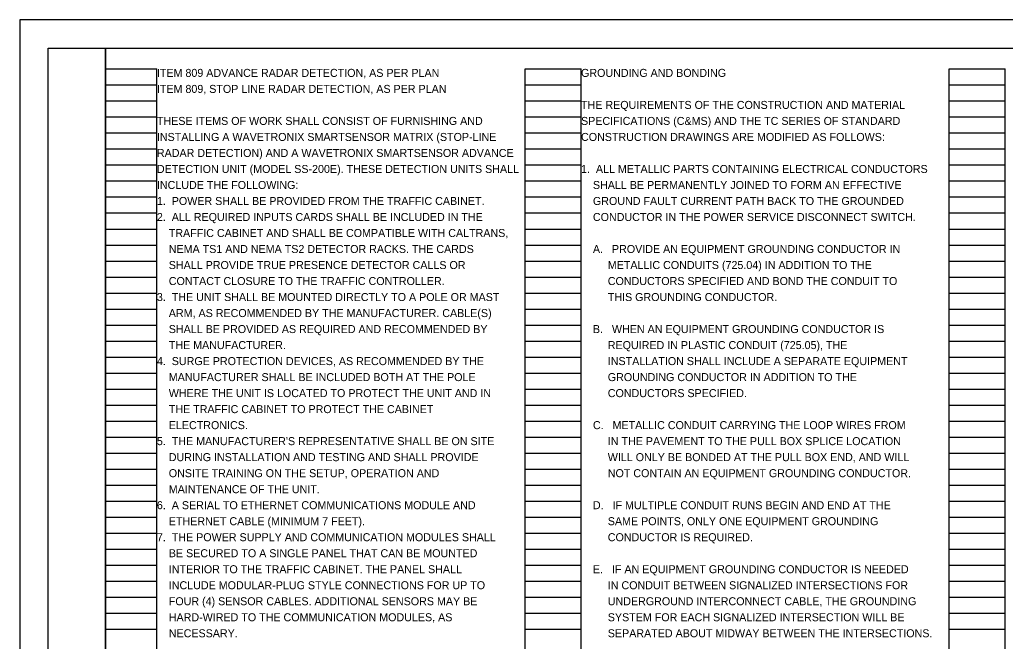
# Model space of a CAD drawing. Extents: x 0 to 34, y 0 to 22.
# Drawn here: x 0 to 17.24, y 11.13 to 22 of the extents above; entities that cross this region are included whole.
import ezdxf

# ---------------------------------------------------------------- set-up
doc = ezdxf.new("R2010")
doc.units = 0
for name, color, linetype in [('SH_Border', 7, 'Continuous'), ('SH_Cut_Line', 7, 'Continuous'), ('SH_Data', 7, 'Continuous'), ('SH_Text', 7, 'Continuous')]:
    doc.layers.add(name, color=color, linetype=linetype)

msp = doc.modelspace()

# ---------------------------------------------------------------- linework, layer by layer
at = {"layer": 'SH_Border'}
for points in [[(0.5, 21.5), (1.5, 21.5), (1.5, 0.5), (0.5, 0.5)], [(1.5, 21.5), (33.5, 21.5), (33.5, 0.5), (1.5, 0.5)]]:
    msp.add_lwpolyline(points, close=True, dxfattribs=at)
at = {"layer": 'SH_Cut_Line'}
msp.add_lwpolyline([(0, 0), (34, 0), (34, 22), (0, 22)], close=True, dxfattribs=at)
at = {"layer": 'SH_Data'}
for p, q in [((1.5, 0.98), (1.5, 21.14)), ((1.5, 21.14), (2.4, 21.14)), ((2.4, 0.98), (2.4, 21.14)), ((8.84, 0.98), (8.84, 21.14)), ((8.84, 21.14), (9.82, 21.14)), ((9.82, 0.98), (9.82, 21.14)), ((16.26, 0.98), (16.26, 21.14)), ((16.26, 21.14), (17.24, 21.14)), ((17.24, 0.98), (17.24, 21.14)), ((1.5, 20.86), (2.4, 20.86)), ((8.84, 20.86), (9.82, 20.86)), ((16.26, 20.86), (17.24, 20.86)), ((1.5, 20.58), (2.4, 20.58)), ((8.84, 20.58), (9.82, 20.58)), ((16.26, 20.58), (17.24, 20.58)), ((1.5, 20.3), (2.4, 20.3)), ((8.84, 20.3), (9.82, 20.3)), ((16.26, 20.3), (17.24, 20.3)), ((1.5, 20.02), (2.4, 20.02)), ((8.84, 20.02), (9.82, 20.02)), ((16.26, 20.02), (17.24, 20.02)), ((1.5, 19.74), (2.4, 19.74)), ((8.84, 19.74), (9.82, 19.74)), ((16.26, 19.74), (17.24, 19.74)), ((1.5, 19.46), (2.4, 19.46)), ((8.84, 19.46), (9.82, 19.46)), ((16.26, 19.46), (17.24, 19.46)), ((1.5, 19.18), (2.4, 19.18)), ((8.84, 19.18), (9.82, 19.18)), ((16.26, 19.18), (17.24, 19.18)), ((1.5, 18.9), (2.4, 18.9)), ((8.84, 18.9), (9.82, 18.9)), ((16.26, 18.9), (17.24, 18.9)), ((1.5, 18.62), (2.4, 18.62)), ((8.84, 18.62), (9.82, 18.62)), ((16.26, 18.62), (17.24, 18.62)), ((1.5, 18.34), (2.4, 18.34)), ((8.84, 18.34), (9.82, 18.34)), ((16.26, 18.34), (17.24, 18.34)), ((1.5, 18.06), (2.4, 18.06)), ((8.84, 18.06), (9.82, 18.06)), ((16.26, 18.06), (17.24, 18.06)), ((1.5, 17.78), (2.4, 17.78)), ((8.84, 17.78), (9.82, 17.78)), ((16.26, 17.78), (17.24, 17.78)), ((1.5, 17.5), (2.4, 17.5)), ((8.84, 17.5), (9.82, 17.5)), ((16.26, 17.5), (17.24, 17.5)), ((1.5, 17.22), (2.4, 17.22)), ((8.84, 17.22), (9.82, 17.22)), ((16.26, 17.22), (17.24, 17.22)), ((1.5, 16.94), (2.4, 16.94)), ((8.84, 16.94), (9.82, 16.94)), ((16.26, 16.94), (17.24, 16.94)), ((1.5, 16.66), (2.4, 16.66)), ((8.84, 16.66), (9.82, 16.66)), ((16.26, 16.66), (17.24, 16.66)), ((1.5, 16.38), (2.4, 16.38)), ((8.84, 16.38), (9.82, 16.38)), ((16.26, 16.38), (17.24, 16.38)), ((1.5, 16.1), (2.4, 16.1)), ((8.84, 16.1), (9.82, 16.1)), ((16.26, 16.1), (17.24, 16.1)), ((1.5, 15.82), (2.4, 15.82)), ((8.84, 15.82), (9.82, 15.82)), ((16.26, 15.82), (17.24, 15.82)), ((1.5, 15.54), (2.4, 15.54)), ((8.84, 15.54), (9.82, 15.54)), ((16.26, 15.54), (17.24, 15.54)), ((1.5, 15.26), (2.4, 15.26)), ((8.84, 15.26), (9.82, 15.26)), ((16.26, 15.26), (17.24, 15.26)), ((1.5, 14.98), (2.4, 14.98)), ((8.84, 14.98), (9.82, 14.98)), ((16.26, 14.98), (17.24, 14.98)), ((1.5, 14.7), (2.4, 14.7)), ((8.84, 14.7), (9.82, 14.7)), ((16.26, 14.7), (17.24, 14.7)), ((1.5, 14.42), (2.4, 14.42)), ((8.84, 14.42), (9.82, 14.42)), ((16.26, 14.42), (17.24, 14.42)), ((1.5, 14.14), (2.4, 14.14)), ((8.84, 14.14), (9.82, 14.14)), ((16.26, 14.14), (17.24, 14.14)), ((1.5, 13.86), (2.4, 13.86)), ((8.84, 13.86), (9.82, 13.86)), ((16.26, 13.86), (17.24, 13.86)), ((1.5, 13.58), (2.4, 13.58)), ((8.84, 13.58), (9.82, 13.58)), ((16.26, 13.58), (17.24, 13.58)), ((1.5, 13.3), (2.4, 13.3)), ((8.84, 13.3), (9.82, 13.3)), ((16.26, 13.3), (17.24, 13.3)), ((1.5, 13.02), (2.4, 13.02)), ((8.84, 13.02), (9.82, 13.02)), ((16.26, 13.02), (17.24, 13.02)), ((1.5, 12.74), (2.4, 12.74)), ((8.84, 12.74), (9.82, 12.74)), ((16.26, 12.74), (17.24, 12.74)), ((1.5, 12.46), (2.4, 12.46)), ((8.84, 12.46), (9.82, 12.46)), ((16.26, 12.46), (17.24, 12.46)), ((1.5, 12.18), (2.4, 12.18)), ((8.84, 12.18), (9.82, 12.18)), ((16.26, 12.18), (17.24, 12.18)), ((1.5, 11.9), (2.4, 11.9)), ((8.84, 11.9), (9.82, 11.9)), ((16.26, 11.9), (17.24, 11.9)), ((1.5, 11.62), (2.4, 11.62)), ((8.84, 11.62), (9.82, 11.62)), ((16.26, 11.62), (17.24, 11.62)), ((1.5, 11.34), (2.4, 11.34)), ((8.84, 11.34), (9.82, 11.34)), ((16.26, 11.34), (17.24, 11.34))]:
    msp.add_line(p, q, dxfattribs=at)

# ---------------------------------------------------------------- texts
at = {"layer": 'SH_Text'}
for s, p in [('ITEM 809 ADVANCE RADAR DETECTION, AS PER PLAN', (2.4, 21)), ('GROUNDING AND BONDING', (9.82, 21)), ('ITEM 809, STOP LINE RADAR DETECTION, AS PER PLAN', (2.4, 20.72)), ('THE REQUIREMENTS OF THE CONSTRUCTION AND MATERIAL', (9.82, 20.44)), ('THESE ITEMS OF WORK SHALL CONSIST OF FURNISHING AND', (2.4, 20.16)), ('SPECIFICATIONS (C&MS) AND THE TC SERIES OF STANDARD', (9.82, 20.16)), ('INSTALLING A WAVETRONIX SMARTSENSOR MATRIX (STOP-LINE', (2.4, 19.88)), ('CONSTRUCTION DRAWINGS ARE MODIFIED AS FOLLOWS:', (9.82, 19.88)), ('RADAR DETECTION) AND A WAVETRONIX SMARTSENSOR ADVANCE', (2.4, 19.6)), ('DETECTION UNIT (MODEL SS-200E). THESE DETECTION UNITS SHALL', (2.4, 19.32)), ('1.  ALL METALLIC PARTS CONTAINING ELECTRICAL CONDUCTORS', (9.82, 19.32)), ('INCLUDE THE FOLLOWING:', (2.4, 19.04)), ('    SHALL BE PERMANENTLY JOINED TO FORM AN EFFECTIVE', (9.82, 19.04)), ('1.  POWER SHALL BE PROVIDED FROM THE TRAFFIC CABINET.', (2.4, 18.76)), ('    GROUND FAULT CURRENT PATH BACK TO THE GROUNDED', (9.82, 18.76)), ('2.  ALL REQUIRED INPUTS CARDS SHALL BE INCLUDED IN THE', (2.4, 18.48)), ('    CONDUCTOR IN THE POWER SERVICE DISCONNECT SWITCH.', (9.82, 18.48)), ('    TRAFFIC CABINET AND SHALL BE COMPATIBLE WITH CALTRANS,', (2.4, 18.2)), ('    NEMA TS1 AND NEMA TS2 DETECTOR RACKS. THE CARDS', (2.4, 17.92)), ('    A.   PROVIDE AN EQUIPMENT GROUNDING CONDUCTOR IN', (9.82, 17.92)), ('    SHALL PROVIDE TRUE PRESENCE DETECTOR CALLS OR', (2.4, 17.64)), ('         METALLIC CONDUITS (725.04) IN ADDITION TO THE', (9.82, 17.64)), ('    CONTACT CLOSURE TO THE TRAFFIC CONTROLLER.', (2.4, 17.36)), ('         CONDUCTORS SPECIFIED AND BOND THE CONDUIT TO', (9.82, 17.36)), ('3.  THE UNIT SHALL BE MOUNTED DIRECTLY TO A POLE OR MAST', (2.4, 17.08)), ('         THIS GROUNDING CONDUCTOR.', (9.82, 17.08)), ('    ARM, AS RECOMMENDED BY THE MANUFACTURER. CABLE(S)', (2.4, 16.8)), ('    SHALL BE PROVIDED AS REQUIRED AND RECOMMENDED BY', (2.4, 16.52)), ('    B.   WHEN AN EQUIPMENT GROUNDING CONDUCTOR IS', (9.82, 16.52)), ('    THE MANUFACTURER.', (2.4, 16.24)), ('         REQUIRED IN PLASTIC CONDUIT (725.05), THE', (9.82, 16.24)), ('4.  SURGE PROTECTION DEVICES, AS RECOMMENDED BY THE', (2.4, 15.96)), ('         INSTALLATION SHALL INCLUDE A SEPARATE EQUIPMENT', (9.82, 15.96)), ('    MANUFACTURER SHALL BE INCLUDED BOTH AT THE POLE', (2.4, 15.68)), ('         GROUNDING CONDUCTOR IN ADDITION TO THE', (9.82, 15.68)), ('    WHERE THE UNIT IS LOCATED TO PROTECT THE UNIT AND IN', (2.4, 15.4)), ('         CONDUCTORS SPECIFIED.', (9.82, 15.4)), ('    THE TRAFFIC CABINET TO PROTECT THE CABINET', (2.4, 15.12)), ('    ELECTRONICS.', (2.4, 14.84)), ('    C.   METALLIC CONDUIT CARRYING THE LOOP WIRES FROM', (9.82, 14.84)), ("5.  THE MANUFACTURER'S REPRESENTATIVE SHALL BE ON SITE", (2.4, 14.56)), ('         IN THE PAVEMENT TO THE PULL BOX SPLICE LOCATION', (9.82, 14.56)), ('    DURING INSTALLATION AND TESTING AND SHALL PROVIDE', (2.4, 14.28)), ('         WILL ONLY BE BONDED AT THE PULL BOX END, AND WILL', (9.82, 14.28)), ('    ONSITE TRAINING ON THE SETUP, OPERATION AND', (2.4, 14)), ('         NOT CONTAIN AN EQUIPMENT GROUNDING CONDUCTOR.', (9.82, 14)), ('    MAINTENANCE OF THE UNIT.', (2.4, 13.72)), ('6.  A SERIAL TO ETHERNET COMMUNICATIONS MODULE AND', (2.4, 13.44)), ('    D.   IF MULTIPLE CONDUIT RUNS BEGIN AND END AT THE', (9.82, 13.44)), ('    ETHERNET CABLE (MINIMUM 7 FEET).', (2.4, 13.16)), ('         SAME POINTS, ONLY ONE EQUIPMENT GROUNDING', (9.82, 13.16)), ('7.  THE POWER SUPPLY AND COMMUNICATION MODULES SHALL', (2.4, 12.88)), ('         CONDUCTOR IS REQUIRED.', (9.82, 12.88)), ('    BE SECURED TO A SINGLE PANEL THAT CAN BE MOUNTED', (2.4, 12.6)), ('    INTERIOR TO THE TRAFFIC CABINET. THE PANEL SHALL', (2.4, 12.32)), ('    E.   IF AN EQUIPMENT GROUNDING CONDUCTOR IS NEEDED', (9.82, 12.32)), ('    INCLUDE MODULAR-PLUG STYLE CONNECTIONS FOR UP TO', (2.4, 12.04)), ('         IN CONDUIT BETWEEN SIGNALIZED INTERSECTIONS FOR', (9.82, 12.04)), ('    FOUR (4) SENSOR CABLES. ADDITIONAL SENSORS MAY BE', (2.4, 11.76)), ('         UNDERGROUND INTERCONNECT CABLE, THE GROUNDING', (9.82, 11.76)), ('    HARD-WIRED TO THE COMMUNICATION MODULES, AS', (2.4, 11.48)), ('         SYSTEM FOR EACH SIGNALIZED INTERSECTION WILL BE', (9.82, 11.48)), ('    NECESSARY.', (2.4, 11.2)), ('         SEPARATED ABOUT MIDWAY BETWEEN THE INTERSECTIONS.', (9.82, 11.2))]:
    msp.add_text(s, height=0.14, dxfattribs=at).set_placement(p)

doc.saveas('drawing.dxf')
